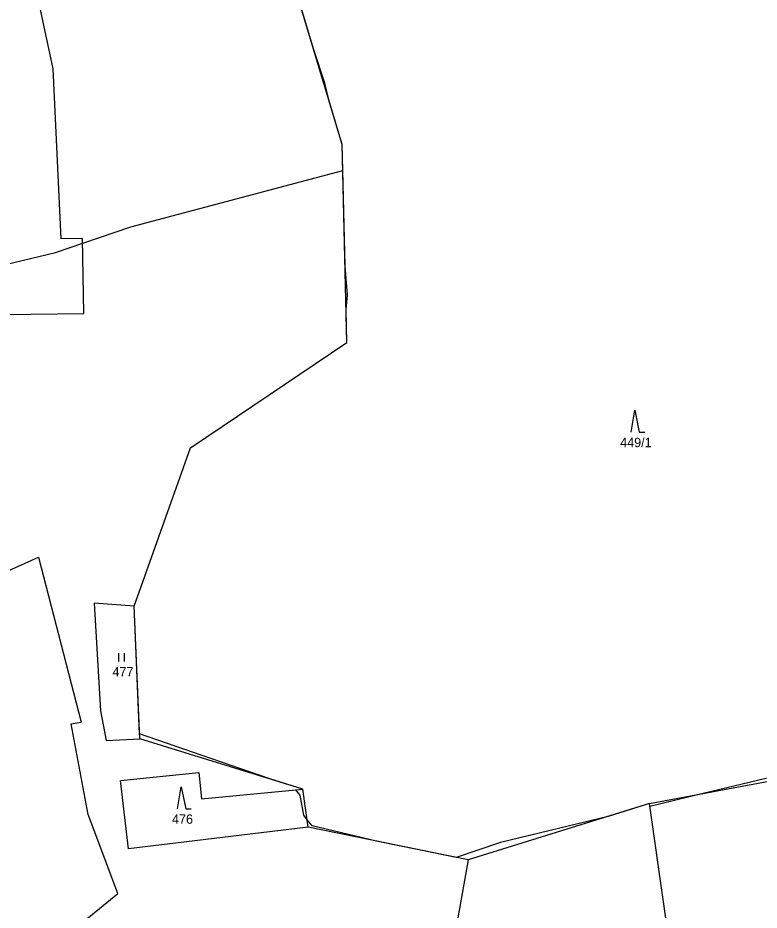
# Model space of a CAD drawing. Extents: x -439246 to -433691, y -1130252 to -1121148.
# Drawn here: x -436683.2 to -436549.1, y -1124471.8 to -1124310.3 of the extents above; entities that cross this region are included whole.
import ezdxf

# ---------------------------------------------------------------- set-up
doc = ezdxf.new("R2010")
doc.units = 0
for name, color, linetype in [('Vrstva 1', 7, 'Continuous'), ('Vrstva 18', 7, 'Continuous'), ('Vrstva 25', 7, 'Continuous'), ('Vrstva 52', 7, 'Continuous')]:
    doc.layers.add(name, color=color, linetype=linetype)

msp = doc.modelspace()

# ---------------------------------------------------------------- linework, layer by layer
at = {"layer": 'Vrstva 1'}
for points in [[(-436624.5, -1124333.27), (-436638.67, -1124286.04)], [(-436676.8, -1124319.53), (-436682.28, -1124293.86)], [(-436675.35, -1124350.32), (-436676.8, -1124319.53)], [(-436623.66, -1124369.06), (-436624.5, -1124333.27)], [(-436671.49, -1124350.26), (-436675.35, -1124350.32)], [(-436671.3, -1124363.81), (-436671.49, -1124350.26)], [(-436700.1, -1124364.21), (-436671.3, -1124363.81)], [(-436651.98, -1124388.12), (-436623.66, -1124369.06)], [(-436662.18, -1124416.77), (-436651.98, -1124388.12)], [(-436703.8, -1124418.8), (-436679.45, -1124407.92)], [(-436679.45, -1124407.92), (-436671.75, -1124437.74)], [(-436662.18, -1124416.77), (-436669.4, -1124416.23)], [(-436669.4, -1124416.23), (-436668.24, -1124435.74)], [(-436661.16, -1124440.78), (-436662.18, -1124416.77)], [(-436668.24, -1124435.74), (-436667.24, -1124441.11)], [(-436673.55, -1124438.08), (-436671.75, -1124437.74)], [(-436670.49, -1124454.47), (-436673.55, -1124438.08)], [(-436667.24, -1124441.11), (-436661.16, -1124440.78)], [(-436631.61, -1124449.9), (-436661.16, -1124440.78)], [(-436664.65, -1124448.3), (-436650.46, -1124446.86)], [(-436650.46, -1124446.86), (-436649.98, -1124451.66)], [(-436663.16, -1124460.68), (-436664.65, -1124448.3)], [(-436568.92, -1124452.5), (-436546.37, -1124448.27)], [(-436649.98, -1124451.66), (-436631.61, -1124449.9)], [(-436630.67, -1124456.75), (-436631.61, -1124449.9)], [(-436568.92, -1124452.5), (-436601.74, -1124462.7)], [(-436558.35, -1124526.63), (-436568.92, -1124452.5)], [(-436665.14, -1124468.74), (-436670.49, -1124454.47)], [(-436630.67, -1124456.75), (-436663.16, -1124460.68)], [(-436601.74, -1124462.7), (-436630.67, -1124456.75)], [(-436601.74, -1124462.7), (-436603.57, -1124473.14)], [(-436679.68, -1124480.63), (-436665.14, -1124468.74)]]:
    msp.add_lwpolyline(points, dxfattribs=at)
at = {"layer": 'Vrstva 25'}
for p, q in [((-436664.94, -1124426.8), (-436664.94, -1124425.3)), ((-436663.94, -1124426.8), (-436663.94, -1124425.3))]:
    msp.add_line(p, q, dxfattribs=at)
for points in [[(-436572.25, -1124385.31), (-436571.55, -1124381.31), (-436570.75, -1124385.31), (-436569.75, -1124385.31)], [(-436654.33, -1124453.45), (-436653.63, -1124449.45), (-436652.83, -1124453.45), (-436651.83, -1124453.45)]]:
    msp.add_lwpolyline(points, dxfattribs=at)
at = {"layer": 'Vrstva 52'}
for points in [[(-436624.39, -1124337.95), (-436624.5, -1124333.27), (-436626.93, -1124325.15), (-436627.63, -1124322.12), (-436629.64, -1124316.14), (-436637.38, -1124290.34)], [(-436824.43, -1124370.98), (-436816.48, -1124372), (-436808.49, -1124373.03), (-436794.35, -1124372.82), (-436794, -1124372.82), (-436792.91, -1124372.93), (-436785.48, -1124373.67), (-436768.01, -1124371.49), (-436765.77, -1124371.21), (-436763.33, -1124370.9), (-436757.96, -1124370.51), (-436752.11, -1124370.08), (-436742.88, -1124369.41), (-436724.98, -1124365.58), (-436722.85, -1124364.95), (-436708.28, -1124360.68), (-436705.6, -1124359.9), (-436703.89, -1124359.4), (-436694.55, -1124357.15), (-436676.41, -1124352.79), (-436671.48, -1124351.1), (-436662.78, -1124348.11), (-436625.29, -1124338.21), (-436624.39, -1124337.95)], [(-436623.66, -1124369.06), (-436623.8, -1124363.07), (-436623.58, -1124360.46), (-436623.98, -1124355.24), (-436624.39, -1124337.95)], [(-436546.6, -1124447.64), (-436559.17, -1124450.67), (-436568.85, -1124453), (-436568.92, -1124452.5), (-436576.4, -1124454.82), (-436595.89, -1124459.52), (-436603.9, -1124462.26), (-436610.67, -1124460.86), (-436618.05, -1124459.34), (-436629.97, -1124456.54), (-436630.85, -1124455.41), (-436631.46, -1124454.62), (-436632.1, -1124451), (-436632.44, -1124450.6), (-436632.78, -1124450.21), (-436632.94, -1124450.03), (-436631.61, -1124449.9), (-436637.62, -1124448.04), (-436649.86, -1124443.82), (-436661.2, -1124439.9), (-436662.18, -1124416.77), (-436651.98, -1124388.12), (-436623.66, -1124369.06)]]:
    msp.add_lwpolyline(points, dxfattribs=at)

# ---------------------------------------------------------------- texts
at = {"layer": 'Vrstva 18'}
for s, p in [('449/1', (-436574.21, -1124388.01)), ('477', (-436666.09, -1124429.5)), ('476', (-436655.31, -1124456.15))]:
    msp.add_text(s, height=1.7, dxfattribs=at).set_placement(p)

doc.saveas('drawing.dxf')
